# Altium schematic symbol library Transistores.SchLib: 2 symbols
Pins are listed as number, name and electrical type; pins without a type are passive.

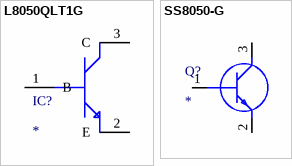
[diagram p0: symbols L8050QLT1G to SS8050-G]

## L8050QLT1G
designator IC?
Integrated Circuit; Manufacturer_Name: LRC; Manufacturer_Part_Number: L8050QLT1G; Description: Trans GP BJT NPN 25V 0.8A 3-Pin SOT-23 T/R
footprint L8050QLT1G
pins: 1 B, 2 E, 3 C

## SS8050-G
designator Q?
Transistor BJT NPN; Manufacturer_Name: Comchip Technology; Manufacturer_Part_Number: SS8050-G
footprint SOT95P240X115-3N
pins: 1 B, 2 E, 3 C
